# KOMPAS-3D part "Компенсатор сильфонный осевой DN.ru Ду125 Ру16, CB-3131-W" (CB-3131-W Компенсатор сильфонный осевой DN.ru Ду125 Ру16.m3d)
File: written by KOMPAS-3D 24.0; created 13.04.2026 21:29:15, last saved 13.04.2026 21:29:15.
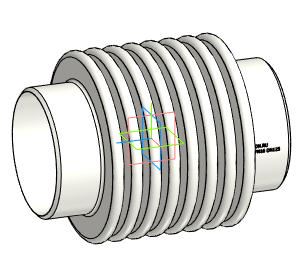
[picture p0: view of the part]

Document properties: Автор: DN.RU; Полное имя файла: D:\PROJECT CAD\DN.RU\...197(ACTUALE). CB-3131-W Компенсатор сильфонный осевой DN.ru\Исходники\DN125\CB-3131-W Компенсатор сильфонный осевой DN.ru Ду125 Ру16.m3d

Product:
- Body: Твердое тело1  | qty 1
    Масса: 3.67219
- Part/product: Компенсатор сильфонный осевой DN.ru Ду125 Ру16  | designation CB-3131-W
    Масса: 2.6
    Раздел спецификации: Прочие изделия
    Комментарий: D140-02125
    Примечание: D140-02125
    additional columns: Типовые

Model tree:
1. Твердое тело1  (labels: Твердое тело1)

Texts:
  CB-3131-W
